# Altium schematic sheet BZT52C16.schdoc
size 127 x 101 mm
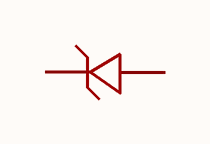
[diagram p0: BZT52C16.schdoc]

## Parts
D?  bzt52c16_c173426  [SOD-123_L2.7-W1.6-LS3.7-RD]  (value not drawn)

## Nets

Not connected (* = marked no-connect by the designer): D? 1(K) 2(A)

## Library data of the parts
D? = bzt52c16_c173426: 二极管配置:1个独立式;稳压值(标称值):16V;稳压值(范围):15.2V~16.8V;耗散功率(Pd):500mW;; Manufacturer: MDD(辰达半导体); AddInBom: yes; ModelId: ad7e39f9e5534b3c96ffdc5532ebb493; ModelName: SOD-123_L2.7-W1.6-H1.4-LS3.7; ModelTransform: 146.026,62.992,0,180,0,0,0.0005,0,0; Diode Configuration: 1个独立式; Zener Voltage(Nom): 16V; Reverse Leakage Current (Ir): 100nA@12V; Pd - Power Dissipation: 500mW; Impedance(Zzt): 40Ω; Tolerance: ±5%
